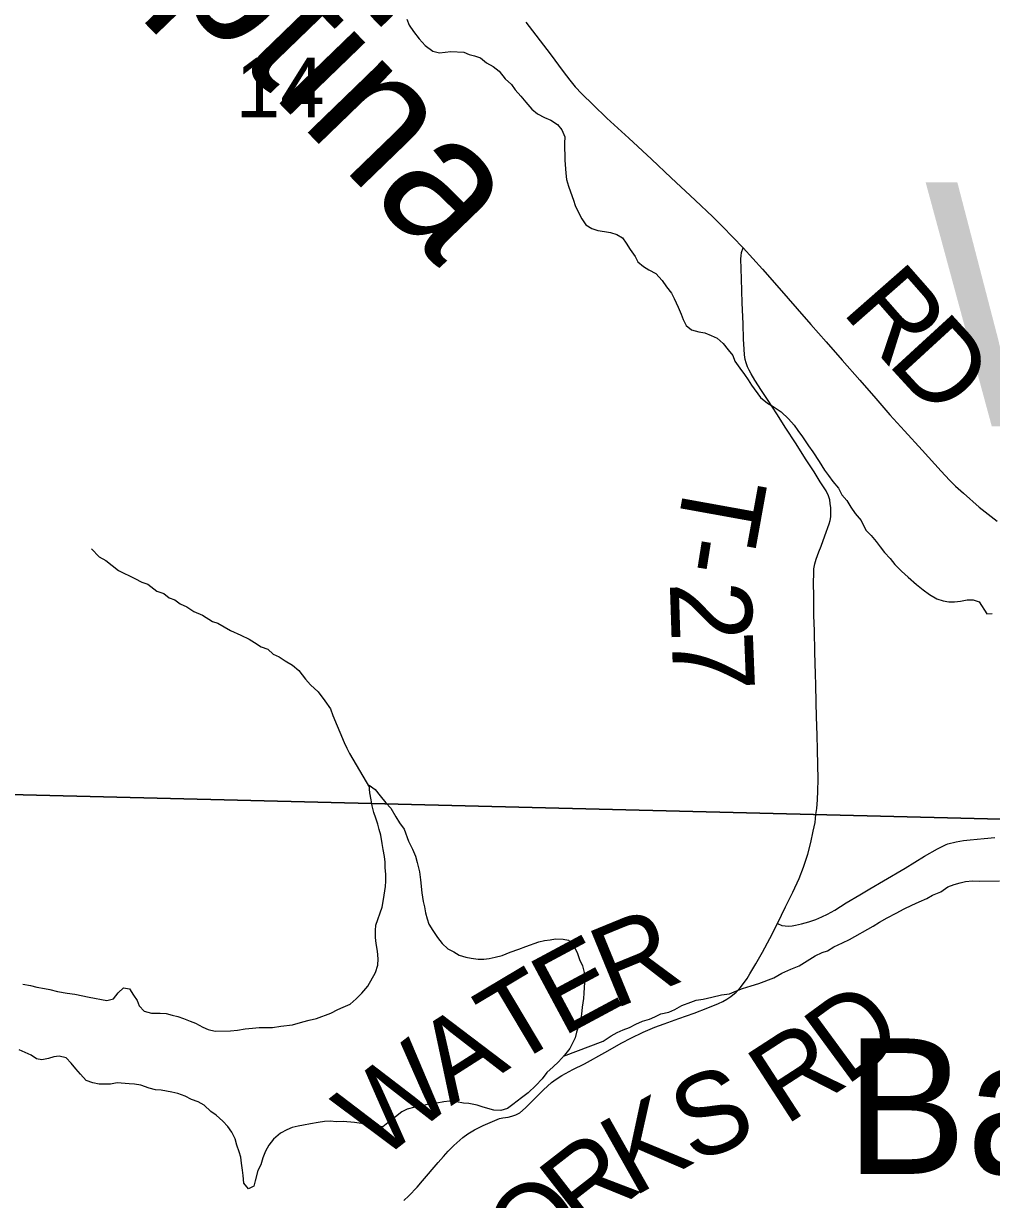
# Model space of a CAD drawing. Extents: x -7.9 to 76.1, y 0 to 22.
# Drawn here: x 2.706 to 3.382, y 19.006 to 19.828 of the extents above; entities that cross this region are included whole.
import ezdxf

# ---------------------------------------------------------------- set-up
doc = ezdxf.new("R2010")
doc.units = 0
for name, color, linetype in [('GM_X_County_Road', 7, 'Continuous'), ('GM_X_County_Road_Text', 7, 'Continuous'), ('GM_X_Minor_Lake', 7, 'Continuous'), ('GM_X_Minor_Lake_Text', 7, 'Continuous'), ('GM_X_Minor_River', 7, 'Continuous'), ('GM_X_Minor_River_Text', 7, 'Continuous'), ('GM_X_Section', 7, 'Continuous'), ('GM_X_Section_Text', 7, 'Continuous'), ('GM_X_Township_Road', 7, 'Continuous'), ('GM_X_Township_Road_Text', 7, 'Continuous'), ('GM_X_Township_Text', 7, 'Continuous')]:
    doc.layers.add(name, color=color, linetype=linetype)

msp = doc.modelspace()

# ---------------------------------------------------------------- linework, layer by layer
at = {"layer": 'GM_X_County_Road'}
msp.add_lwpolyline([(3.05661, 19.82874), (3.07362, 19.80663), (3.08275, 19.79429), (3.08743, 19.78821), (3.09122, 19.78369), (3.09582, 19.77884), (3.10371, 19.77103), (3.11341, 19.76166), (3.12878, 19.74777), (3.14448, 19.73314), (3.15837, 19.72006), (3.17494, 19.70449), (3.18731, 19.69286), (3.19413, 19.68603), (3.20868, 19.67116), (3.22208, 19.65628), (3.23362, 19.64305), (3.24633, 19.62849), (3.25593, 19.61753), (3.26647, 19.6055), (3.27775, 19.59261), (3.29004, 19.57857), (3.30123, 19.56578), (3.31111, 19.55451), (3.32135, 19.54321), (3.33365, 19.52964), (3.34695, 19.51497), (3.3527, 19.50881), (3.35698, 19.50453), (3.36248, 19.4996), (3.3735, 19.4899), (3.38599, 19.48012)], dxfattribs=at)
at = {"layer": 'GM_X_Minor_Lake'}
for points in [[(2.95839, 19.24189), (2.95795, 19.24568), (2.95711, 19.25059), (2.95628, 19.25475), (2.95542, 19.2608), (2.95422, 19.26457), (2.95339, 19.26834), (2.95181, 19.27249), (2.9506, 19.27663), (2.94939, 19.28116), (2.94856, 19.28532), (2.94772, 19.29023), (2.94725, 19.29553), (2.95146, 19.29258), (2.95495, 19.28809), (2.95881, 19.28323), (2.96228, 19.2795), (2.96579, 19.27349), (2.96851, 19.26937), (2.97162, 19.26488), (2.97479, 19.25659), (2.97754, 19.25095), (2.97951, 19.24606), (2.98073, 19.24153), (2.98235, 19.23512), (2.98321, 19.22944), (2.98412, 19.22036), (2.98498, 19.21431), (2.9858, 19.21053), (2.98663, 19.20638), (2.98784, 19.20223), (2.98904, 19.19846), (2.99177, 19.19395), (2.99488, 19.18908), (2.99836, 19.18497), (3.0022, 19.18125), (3.00641, 19.17905), (3.01023, 19.17684), (3.01479, 19.17541), (3.01859, 19.17472), (3.02352, 19.17405), (3.0273, 19.17412), (3.03108, 19.17456), (3.03523, 19.17539), (3.04012, 19.17662), (3.04576, 19.17899), (3.05178, 19.181), (3.05666, 19.18298), (3.06569, 19.18617), (3.06984, 19.18701), (3.07362, 19.18745), (3.07738, 19.18828), (3.08269, 19.18799), (3.08648, 19.1873), (3.09034, 19.1832), (3.09269, 19.17869), (3.09428, 19.17379), (3.09625, 19.16928), (3.09747, 19.16475), (3.09759, 19.15793), (3.09734, 19.15034), (3.09703, 19.14654), (3.096, 19.14046), (3.0957, 19.13552), (3.09502, 19.13134), (3.09357, 19.12752), (3.09214, 19.12294), (3.09107, 19.11913), (3.08742, 19.11149), (3.08371, 19.10687), (3.07963, 19.10225), (3.07591, 19.09877), (3.07144, 19.0949), (3.06811, 19.09029), (3.06365, 19.08566), (3.05844, 19.08063), (3.05358, 19.07714), (3.04761, 19.07248), (3.04387, 19.06976), (3.03936, 19.06816), (3.03443, 19.06845), (3.02683, 19.07059), (3.02264, 19.07203), (3.01695, 19.07307), (3.01316, 19.07338), (3.00822, 19.07443), (3.0033, 19.07472), (2.99952, 19.07427), (2.99462, 19.07343), (2.98782, 19.07255), (2.98368, 19.07134), (2.97915, 19.0705), (2.97387, 19.06926), (2.97012, 19.0673), (2.96565, 19.06381), (2.96154, 19.0607), (2.95669, 19.05683), (2.95252, 19.05675), (2.9472, 19.05817), (2.94189, 19.05921), (2.93696, 19.05988)], [(2.70521, 19.15659), (2.71053, 19.15555), (2.71509, 19.1545), (2.7204, 19.15345), (2.7242, 19.15276), (2.72952, 19.15134), (2.73635, 19.15033), (2.74166, 19.14966), (2.75153, 19.14757), (2.75533, 19.14687), (2.76027, 19.14583), (2.76406, 19.14514), (2.76858, 19.14635), (2.77191, 19.15059), (2.77564, 19.15406), (2.77981, 19.15338), (2.78254, 19.14888), (2.78525, 19.14514), (2.78645, 19.14137), (2.78993, 19.13764), (2.79525, 19.13622), (2.8013, 19.13632), (2.80547, 19.13602), (2.80965, 19.13496), (2.81345, 19.13389), (2.81764, 19.13245), (2.82221, 19.13063), (2.82602, 19.12919), (2.83098, 19.12662), (2.8348, 19.12479), (2.83973, 19.12374), (2.85033, 19.12393), (2.85524, 19.1244), (2.86052, 19.12525), (2.86581, 19.12573), (2.87034, 19.12619), (2.8798, 19.12636), (2.88546, 19.12722), (2.89377, 19.12812), (2.90092, 19.13015), (2.90544, 19.13137), (2.91034, 19.13259), (2.9205, 19.13619), (2.92537, 19.13892), (2.92912, 19.14051), (2.93401, 19.14249), (2.9381, 19.14636), (2.9422, 19.15022), (2.94627, 19.15523), (2.95178, 19.1648), (2.95321, 19.16976), (2.95351, 19.17431), (2.95304, 19.17961), (2.95219, 19.18491), (2.95174, 19.18907), (2.95166, 19.194), (2.95197, 19.19779), (2.95629, 19.21038), (2.95734, 19.21571), (2.95869, 19.22483), (2.959, 19.22863), (2.95892, 19.23318), (2.95846, 19.2381), (2.95839, 19.24189)], [(2.93696, 19.05988), (2.929, 19.0605), (2.92408, 19.06041), (2.92029, 19.06072), (2.91613, 19.06065), (2.9116, 19.05981), (2.90632, 19.05896), (2.90142, 19.05811), (2.89765, 19.05728), (2.8935, 19.05645), (2.88974, 19.05487), (2.88524, 19.05251), (2.8804, 19.04826), (2.87707, 19.04402), (2.87487, 19.03981), (2.87306, 19.03523), (2.87163, 19.03027), (2.86942, 19.02644), (2.86766, 19.01921), (2.86659, 19.0154), (2.86284, 19.01343), (2.85974, 19.01755), (2.85927, 19.02285), (2.85883, 19.02663), (2.85798, 19.03155), (2.85753, 19.03571), (2.85633, 19.03948), (2.85474, 19.044), (2.85353, 19.04853), (2.85118, 19.05304), (2.84846, 19.05716), (2.84499, 19.06089), (2.84038, 19.06498), (2.83655, 19.06757), (2.83193, 19.07203), (2.82773, 19.07423), (2.82316, 19.07605), (2.81858, 19.07824), (2.81363, 19.08005), (2.80945, 19.08111), (2.80186, 19.08249), (2.79807, 19.0828), (2.79351, 19.08386), (2.78779, 19.08603), (2.78324, 19.08671), (2.77945, 19.08702), (2.77112, 19.08763), (2.76659, 19.08679), (2.75865, 19.08665), (2.75409, 19.0877), (2.74952, 19.08914), (2.74566, 19.09362), (2.74219, 19.09735), (2.73909, 19.10146), (2.73562, 19.10519), (2.73068, 19.10624), (2.72691, 19.10579), (2.72314, 19.10459), (2.71862, 19.10375), (2.71482, 19.10444), (2.71099, 19.10702), (2.7026, 19.11066)]]:
    msp.add_lwpolyline(points, dxfattribs=at)
at = {"layer": 'GM_X_Minor_River'}
for points in [[(2.97355, 19.83096), (2.97513, 19.82682), (2.97824, 19.82233), (2.98211, 19.81708), (2.98635, 19.81261), (2.99172, 19.80854), (2.99628, 19.80748), (3.00421, 19.80838), (3.0133, 19.80778), (3.01711, 19.80633), (3.02091, 19.80527), (3.0251, 19.80382), (3.02932, 19.80049), (3.03391, 19.79791), (3.03813, 19.79458), (3.04238, 19.78934), (3.04661, 19.78525), (3.04933, 19.78151), (3.05319, 19.77703), (3.05666, 19.77292), (3.06091, 19.76807), (3.06475, 19.76472), (3.06972, 19.76216), (3.07429, 19.76034), (3.07888, 19.75739), (3.08197, 19.75366), (3.08395, 19.74876), (3.08365, 19.74421), (3.08385, 19.73246), (3.08477, 19.72337), (3.08522, 19.71883), (3.08644, 19.7143), (3.08802, 19.71016), (3.09001, 19.70451), (3.09121, 19.70074), (3.09357, 19.69586), (3.09591, 19.69135), (3.09864, 19.68723), (3.10284, 19.68465), (3.10703, 19.68321), (3.11158, 19.68253), (3.11576, 19.68184), (3.12032, 19.68041), (3.12415, 19.6782), (3.12686, 19.67446), (3.12959, 19.66996), (3.13308, 19.66509), (3.13503, 19.66133), (3.13887, 19.65799), (3.1427, 19.65578), (3.14766, 19.65322)], [(3.14766, 19.65322), (3.15191, 19.64836), (3.15501, 19.64387), (3.15849, 19.63938), (3.16045, 19.63562), (3.1632, 19.62961), (3.16518, 19.62471), (3.16676, 19.62095), (3.16872, 19.61682), (3.17256, 19.61385), (3.1775, 19.61242), (3.18168, 19.61174), (3.18625, 19.60992), (3.19044, 19.6081), (3.19467, 19.60439), (3.19815, 19.5999), (3.20125, 19.59578), (3.20283, 19.59202), (3.20632, 19.58715), (3.20942, 19.58266), (3.21214, 19.57892), (3.21447, 19.57517), (3.22068, 19.56656), (3.22566, 19.56248), (3.22949, 19.56027), (3.23523, 19.55658), (3.24023, 19.55174), (3.24409, 19.54726), (3.24681, 19.54351), (3.24991, 19.53902), (3.25418, 19.53265), (3.25728, 19.52854), (3.26156, 19.52179), (3.26545, 19.51579), (3.26816, 19.51205), (3.27126, 19.50793), (3.27513, 19.50307), (3.27748, 19.49856), (3.28095, 19.49445), (3.28368, 19.48995), (3.28679, 19.48546), (3.29103, 19.48061), (3.29418, 19.47384), (3.29802, 19.47012), (3.3015, 19.46601), (3.30421, 19.46226), (3.30731, 19.45815), (3.31117, 19.45405), (3.31464, 19.44994), (3.31927, 19.44509), (3.32388, 19.441), (3.32965, 19.4358), (3.33425, 19.43208), (3.33885, 19.42876), (3.34382, 19.42581), (3.34839, 19.42437), (3.35218, 19.42368), (3.35634, 19.42376), (3.3605, 19.42421), (3.36502, 19.42505), (3.36919, 19.42512), (3.37337, 19.42368), (3.37881, 19.41544), (3.38259, 19.4155)], [(2.7533, 19.46079), (2.75869, 19.45519), (2.76327, 19.45262), (2.7721, 19.44558), (2.78355, 19.4401), (2.78851, 19.43753), (2.7927, 19.43609), (2.79884, 19.43127), (2.80379, 19.42946), (2.80762, 19.4265), (2.81143, 19.42505), (2.81526, 19.42246), (2.81984, 19.42027), (2.82481, 19.41695), (2.83091, 19.41441), (2.8378, 19.40998), (2.8416, 19.40891), (2.8504, 19.40376), (2.85764, 19.40048), (2.86337, 19.39755), (2.86719, 19.39534), (2.87178, 19.39239), (2.87635, 19.39057), (2.8802, 19.38723), (2.88439, 19.38541), (2.8886, 19.38245), (2.89358, 19.37951), (2.89818, 19.3758), (2.90282, 19.36981), (2.9063, 19.3657), (2.91168, 19.36087), (2.91633, 19.35451), (2.92022, 19.34889), (2.9218, 19.34437), (2.9297, 19.32555), (2.93166, 19.32142), (2.93362, 19.31766), (2.94737, 19.29411)], [(3.08311, 19.10619), (3.11079, 19.11683), (3.1164, 19.12034), (3.12052, 19.12269), (3.12465, 19.12466), (3.12916, 19.12626), (3.13366, 19.12861), (3.13817, 19.13059), (3.14306, 19.13219), (3.14682, 19.13378), (3.15095, 19.13575), (3.1566, 19.13699), (3.16073, 19.13895), (3.1656, 19.1417), (3.17199, 19.14408), (3.17576, 19.14529), (3.18066, 19.14614), (3.18669, 19.14738), (3.19347, 19.14902), (3.19913, 19.14988), (3.20402, 19.15186), (3.20816, 19.15345), (3.21417, 19.15545), (3.21944, 19.15706), (3.22997, 19.16104), (3.23559, 19.16418), (3.24198, 19.16694), (3.24761, 19.16932), (3.25323, 19.17283), (3.25884, 19.17634), (3.26372, 19.1787), (3.26748, 19.17991), (3.27198, 19.18264), (3.27798, 19.1854), (3.28286, 19.18776), (3.29935, 19.19716), (3.30384, 19.19989), (3.30908, 19.20302), (3.31546, 19.20616), (3.32108, 19.2093), (3.32634, 19.21166), (3.3316, 19.21403), (3.33685, 19.2164), (3.34097, 19.21875), (3.34661, 19.22112), (3.35147, 19.22462), (3.35598, 19.22622), (3.36012, 19.22743), (3.36389, 19.22826), (3.3688, 19.22872), (3.37373, 19.22843), (3.38772, 19.22868)]]:
    msp.add_lwpolyline(points, dxfattribs=at)
at = {"layer": 'GM_X_Section'}
for points in [[(3.44816, 20.29633), (3.41682, 19.27112), (2.40571, 19.29621), (2.42909, 20.32093)], [(3.41682, 19.27112), (3.38904, 18.26227), (2.38104, 18.28209), (2.40571, 19.29621)]]:
    msp.add_lwpolyline(points, close=True, dxfattribs=at)
at = {"layer": 'GM_X_Township_Road'}
for points in [[(3.23263, 19.19905), (3.23815, 19.21065), (3.24324, 19.22084), (3.24778, 19.23042), (3.25081, 19.23823), (3.25377, 19.24752), (3.25583, 19.25557), (3.25756, 19.26338), (3.25879, 19.26963), (3.25945, 19.27506), (3.26001, 19.27936), (3.26051, 19.28533), (3.26084, 19.29174), (3.26091, 19.29967), (3.2606, 19.32042), (3.26034, 19.33066), (3.25992, 19.34345), (3.25959, 19.35335), (3.25928, 19.36564), (3.25909, 19.37315), (3.25869, 19.38853), (3.25831, 19.40337), (3.25804, 19.41426), (3.25785, 19.42708), (3.25771, 19.4376), (3.25787, 19.44336), (3.25804, 19.44681), (3.25853, 19.45027), (3.25951, 19.45363), (3.26141, 19.45865), (3.26305, 19.46276), (3.26561, 19.46989), (3.26864, 19.47822), (3.2693, 19.48068), (3.26971, 19.48306), (3.26987, 19.48569), (3.26972, 19.48936), (3.26946, 19.49243), (3.26905, 19.49498), (3.26814, 19.49786), (3.2665, 19.50139), (3.26422, 19.50483), (3.26246, 19.50766), (3.25806, 19.51454), (3.25269, 19.52295), (3.24512, 19.5348), (3.23847, 19.54521), (3.23206, 19.55502), (3.22595, 19.56437), (3.22129, 19.57151), (3.21669, 19.57867), (3.21406, 19.58318), (3.21266, 19.58573), (3.21167, 19.58796), (3.21069, 19.59066), (3.21003, 19.59313), (3.20957, 19.59628), (3.20921, 19.60028), (3.20888, 19.60719), (3.20849, 19.61813), (3.20798, 19.63259), (3.20739, 19.64953), (3.20691, 19.66333), (3.20707, 19.66563), (3.20748, 19.66785), (3.20868, 19.67116)], [(3.29711, 19.22308), (3.30664, 19.22886), (3.32184, 19.23773), (3.33536, 19.24612), (3.34424, 19.25105), (3.35046, 19.25418), (3.35165, 19.2546), (3.35737, 19.25613), (3.36241, 19.25703), (3.36715, 19.25753), (3.37692, 19.25826), (3.38448, 19.25904)], [(2.9715, 19.00546), (2.97502, 19.00859), (2.98069, 19.01471), (2.98461, 19.01917), (2.99549, 19.03198), (2.99918, 19.03606), (3.00247, 19.03976), (3.00641, 19.04391), (3.01268, 19.04946), (3.01612, 19.05197), (3.02083, 19.0548), (3.0268, 19.05775), (3.03675, 19.0621), (3.03841, 19.06261), (3.04062, 19.06306), (3.0444, 19.06367), (3.04686, 19.06425), (3.04965, 19.06523), (3.05245, 19.06671), (3.05652, 19.07009), (3.05889, 19.07236), (3.06895, 19.08266), (3.07174, 19.08529), (3.07473, 19.08776), (3.07791, 19.0901), (3.08194, 19.09273), (3.08966, 19.09686), (3.09777, 19.10091), (3.11196, 19.1088), (3.12368, 19.1155), (3.13003, 19.1189), (3.13863, 19.12296), (3.1468, 19.1264), (3.15327, 19.12884), (3.16367, 19.13252), (3.17444, 19.13634), (3.18391, 19.14002), (3.19129, 19.14304), (3.19431, 19.14445), (3.19719, 19.14607), (3.19989, 19.14791), (3.20375, 19.15108), (3.20641, 19.15405), (3.20814, 19.15598), (3.21126, 19.16042), (3.21332, 19.16379), (3.21734, 19.17078), (3.22203, 19.17891), (3.22721, 19.18837), (3.23263, 19.19905), (3.23552, 19.19762), (3.23783, 19.19721), (3.24054, 19.19713), (3.24284, 19.19737), (3.24523, 19.19787), (3.24925, 19.1988), (3.25443, 19.20009), (3.25926, 19.20168), (3.26347, 19.20354), (3.26746, 19.20547), (3.27265, 19.20836), (3.28063, 19.21332), (3.29018, 19.21888), (3.29711, 19.22308)]]:
    msp.add_lwpolyline(points, dxfattribs=at)

# ---------------------------------------------------------------- texts
at = {"layer": 'GM_X_County_Road_Text'}
for s, rotation, p in [('R', 311.29938, (3.27666, 19.6266)), ('D', 312.53707, (3.30834, 19.59056))]:
    msp.add_text(s, height=0.05682, rotation=rotation, dxfattribs=at).set_placement(p)
at = {"layer": 'GM_X_Minor_Lake_Text'}
msp.add_text('Barnesville', height=0.0946928, rotation=0.00297, dxfattribs=at).set_placement((3.28024, 19.02395))
at = {"layer": 'GM_X_Minor_River_Text'}
msp.add_text('Captina', height=0.094674, rotation=314.06289, dxfattribs=at).set_placement((2.69267, 19.97034))
at = {"layer": 'GM_X_Section_Text'}
msp.add_text('14', height=0.041856, rotation=0.00001, dxfattribs=at).set_placement((2.85399, 19.76228))
at = {"layer": 'GM_X_Township_Road_Text'}
for s, rotation, p in [('T', 259.74996, (3.16946, 19.51537)), ('-', 260.95187, (3.16168, 19.47227)), ('2', 271.86674, (3.15728, 19.43746)), ('7', 272.32494, (3.15844, 19.40198)), ('R', 22.26019, (3.11799, 19.13874)), ('E', 28.22122, (3.08196, 19.11931)), ('T', 30.80647, (3.04604, 19.09788)), ('D', 36.25948, (3.27989, 19.08462)), ('A', 32.5483, (3.00428, 19.07122)), ('R', 32.93359, (3.23776, 19.05721)), ('W', 38.09895, (2.95366, 19.03144)), ('S', 21.78906, (3.1731, 19.03094)), ('K', 29.40736, (3.13134, 19.00725)), ('R', 37.88628, (3.09636, 18.97982)), ('O', 39.1815, (3.05787, 18.94844))]:
    msp.add_text(s, height=0.05682, rotation=rotation, dxfattribs=at).set_placement(p)
at = {"layer": 'GM_X_Township_Text'}
msp.add_text('WARREN', height=0.170455, rotation=0.00001, dxfattribs=at).set_placement((3.33505, 19.5465))

doc.saveas('drawing.dxf')
